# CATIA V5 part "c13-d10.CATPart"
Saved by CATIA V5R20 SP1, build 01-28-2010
Part number: Part1
Bounding box of the stored display mesh (mm): x -49.986 to 49.986, y -49.986 to 49.986, z 0 to 320
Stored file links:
  D:\v5_r20\psrt_files_downloaded\c13-catia-v5r20-prt\c13-catia-v5r20-figr-13-37 & 38\c13-d10.CATPart
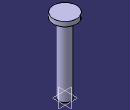
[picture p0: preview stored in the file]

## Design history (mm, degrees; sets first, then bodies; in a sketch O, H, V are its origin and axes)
Body1 (main body)
  Sketch1 on yz-plane, origin (0, 0, 0), H (0, 1, 0), V (0, 0, 1)
    axis line L1 (0, 0) -> (0, 409.3493)
    line L2 (0, 0) -> (25, 0)
    line L3 (25, 0) -> (25, 300)
    line L4 (25, 300) -> (50, 300)
    line L5 (50, 300) -> (50, 320)
    line L6 (50, 320) -> (0, 320)
    point P6 (0, 320)
    line L7 (0, 320) -> (0, 0)
    "Radius" L5 L1 = 50
    "Radius" L3 L1 = 25
    length L3 = 300
    length L5 = 20
    vertical: L1 V, L3 V, L5 V, L7 V
    horizontal: L2 H, L4 H, L6 H
    coincidence: P6 L1
  Shaft1: profile Sketch1, axis Sketch1.L1, angle 360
